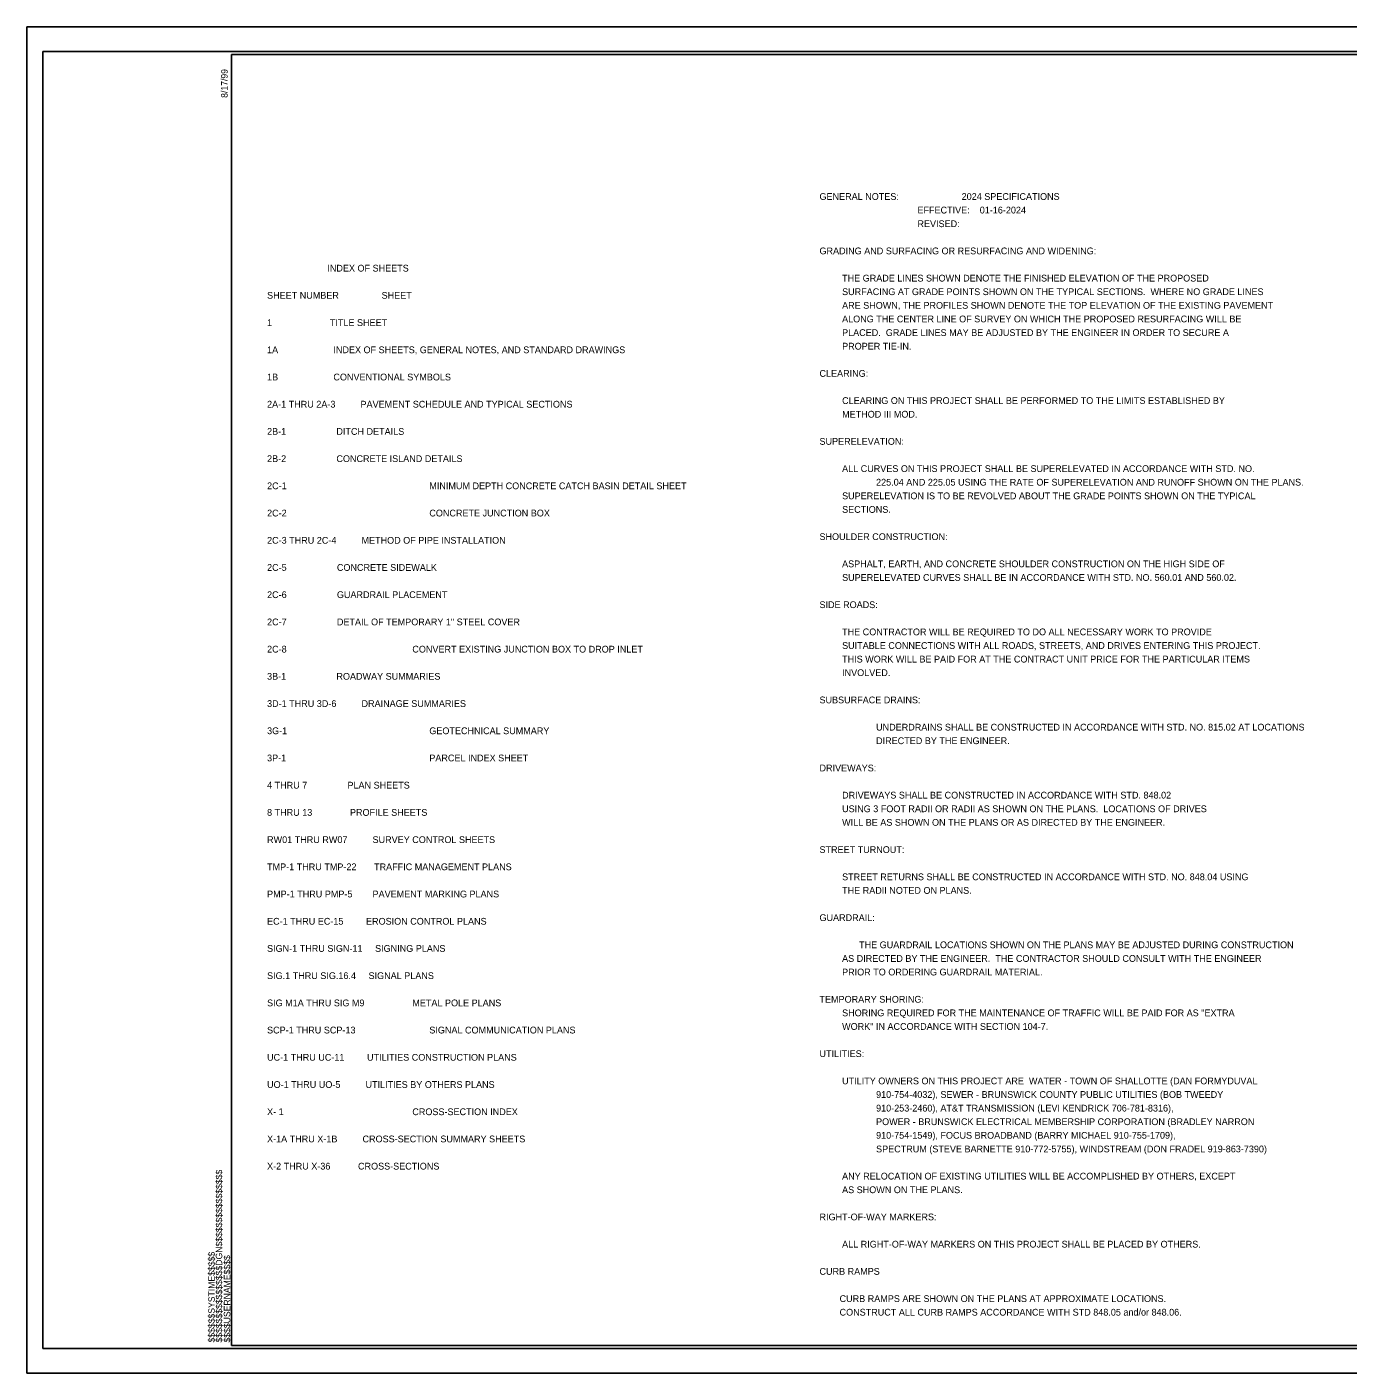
# Model space of a CAD drawing. Extents: x 779200 to 786346, y 600107 to 602297.
# Drawn here: x 780770 to 782920, y 600107 to 602297 of the extents above; entities that cross this region are included whole.
import ezdxf

# ---------------------------------------------------------------- set-up
doc = ezdxf.new("R2010")
doc.units = 0
for name, color, linetype in [('Sheet Border Standard 30in CELL', 7, 'Continuous'), ('Sheet Data Field CELL', 7, 'Continuous'), ('Sheet Plot Border Inside CELL', 7, 'Continuous'), ('Sheet Sticker Preliminary CELL', 7, 'Continuous')]:
    doc.layers.add(name, color=color, linetype=linetype)

msp = doc.modelspace()

# ---------------------------------------------------------------- linework, layer by layer
at = {"layer": 'Sheet Border Standard 30in CELL'}
msp.add_line((781103.3, 602251.7), (781103.3, 602251.7), dxfattribs=at)
msp.add_lwpolyline([(784103.3, 602251.7), (781103.3, 602251.7), (781103.3, 600151.7), (784103.3, 600151.7)], close=True, dxfattribs=at)
at = {"layer": 'Sheet Data Field CELL'}
msp.add_lwpolyline([(780770.3, 600106.7), (784137.3, 600106.7), (784137.3, 602296.7), (780770.3, 602296.7)], close=True, dxfattribs=at)
at = {"layer": 'Sheet Plot Border Inside CELL'}
msp.add_lwpolyline([(780796.3, 600146.7), (784128.3, 600146.7), (784128.3, 602256.7), (780796.3, 602256.7)], close=True, dxfattribs=at)

# ---------------------------------------------------------------- texts
at = {"layer": 'Sheet Border Standard 30in CELL'}
for s, p in [('8/17/99', (781096.8, 602181.3)), ('$$$$$$$$$$$$$$$$DGN$$$$$$$$$$$$$$$$', (781088, 600156.4)), ('$$$$$$SYSTIME$$$$$', (781075.9, 600156.4)), ('$$$$USERNAME$$$$', (781101.1, 600156.4))]:
    msp.add_text(s, height=10.5, rotation=90, dxfattribs=at).set_placement(p)
at = {"layer": 'Sheet Sticker Preliminary CELL'}
for s, p in [('GENERAL NOTES:                         2024 SPECIFICATIONS', (782059.8, 602015.3)), ('                                       EFFECTIVE:    01-16-2024', (782059.8, 601993.2)), ('                                       REVISED:      ', (782059.8, 601971)), ('GRADING AND SURFACING OR RESURFACING AND WIDENING:  ', (782059.8, 601926.8)), ('                        INDEX OF SHEETS ', (781161, 601898.7)), ('         THE GRADE LINES SHOWN DENOTE THE FINISHED ELEVATION OF THE PROPOSED ', (782059.8, 601882.5)), ('SHEET NUMBER                 SHEET   ', (781161, 601854.5)), ('         SURFACING AT GRADE POINTS SHOWN ON THE TYPICAL SECTIONS.  WHERE NO GRADE LINES ', (782059.8, 601860.4)), ('         ARE SHOWN, THE PROFILES SHOWN DENOTE THE TOP ELEVATION OF THE EXISTING PAVEMENT ', (782059.8, 601838.2)), ('1                       TITLE SHEET', (781161, 601810.2)), ('         ALONG THE CENTER LINE OF SURVEY ON WHICH THE PROPOSED RESURFACING WILL BE ', (782059.8, 601816.1)), ('         PLACED.  GRADE LINES MAY BE ADJUSTED BY THE ENGINEER IN ORDER TO SECURE A ', (782059.8, 601793.9)), ('1A                      INDEX OF SHEETS, GENERAL NOTES, AND STANDARD DRAWINGS', (781161, 601765.9)), ('         PROPER TIE-IN.  ', (782059.8, 601771.8)), ('1B                      CONVENTIONAL SYMBOLS ', (781161, 601721.6)), ('CLEARING:  ', (782059.8, 601727.5)), ('2A-1 THRU 2A-3          PAVEMENT SCHEDULE AND TYPICAL SECTIONS', (781161, 601677.4)), ('         CLEARING ON THIS PROJECT SHALL BE PERFORMED TO THE LIMITS ESTABLISHED BY ', (782059.8, 601683.3)), ('         METHOD III MOD.', (782059.8, 601661.1)), ('2B-1                    DITCH DETAILS', (781161, 601633.1)), ('SUPERELEVATION:  ', (782059.8, 601616.9)), ('2B-2                    CONCRETE ISLAND DETAILS', (781161, 601588.8)), ('         ALL CURVES ON THIS PROJECT SHALL BE SUPERELEVATED IN ACCORDANCE WITH STD. NO.', (782059.8, 601572.6)), ('2C-1 ', (781161, 601544.6)), ('MINIMUM DEPTH CONCRETE CATCH BASIN DETAIL SHEET', (781425, 601544.6)), (' 225.04 AND 225.05 USING THE RATE OF SUPERELEVATION AND RUNOFF SHOWN ON THE PLANS.', (782147.8, 601550.5)), ('         SUPERELEVATION IS TO BE REVOLVED ABOUT THE GRADE POINTS SHOWN ON THE TYPICAL ', (782059.8, 601528.3)), ('2C-2 ', (781161, 601500.3)), ('CONCRETE JUNCTION BOX', (781425, 601500.3)), ('         SECTIONS.  ', (782059.8, 601506.2)), ('2C-3 THRU 2C-4          METHOD OF PIPE INSTALLATION', (781161, 601456)), ('SHOULDER CONSTRUCTION:  ', (782059.8, 601461.9)), ('2C-5                    CONCRETE SIDEWALK', (781161, 601411.8)), ('         ASPHALT, EARTH, AND CONCRETE SHOULDER CONSTRUCTION ON THE HIGH SIDE OF', (782059.8, 601417.7)), ('         SUPERELEVATED CURVES SHALL BE IN ACCORDANCE WITH STD. NO. 560.01 AND 560.02.', (782059.8, 601395.5)), ('2C-6                    GUARDRAIL PLACEMENT', (781161, 601367.5)), ('SIDE ROADS:  ', (782059.8, 601351.2)), ('2C-7                    DETAIL OF TEMPORARY 1" STEEL COVER', (781161, 601323.2)), ('         THE CONTRACTOR WILL BE REQUIRED TO DO ALL NECESSARY WORK TO PROVIDE ', (782059.8, 601307)), ('2C-8', (781161, 601278.9)), ('    CONVERT EXISTING JUNCTION BOX TO DROP INLET ', (781381, 601278.9)), ('         SUITABLE CONNECTIONS WITH ALL ROADS, STREETS, AND DRIVES ENTERING THIS PROJECT.  ', (782059.8, 601284.8)), ('         THIS WORK WILL BE PAID FOR AT THE CONTRACT UNIT PRICE FOR THE PARTICULAR ITEMS ', (782059.8, 601262.7)), ('3B-1                    ROADWAY SUMMARIES', (781161, 601234.7)), ('         INVOLVED.', (782059.8, 601240.6)), ('3D-1 THRU 3D-6          DRAINAGE SUMMARIES', (781161, 601190.4)), ('SUBSURFACE DRAINS:', (782059.8, 601196.3)), ('3G-1', (781161, 601146.1)), ('GEOTECHNICAL SUMMARY', (781425, 601146.1)), (' UNDERDRAINS SHALL BE CONSTRUCTED IN ACCORDANCE WITH STD. NO. 815.02 AT LOCATIONS', (782147.8, 601152)), (' DIRECTED BY THE ENGINEER.   ', (782147.8, 601129.9)), ('3P-1                    ', (781161, 601101.9)), ('PARCEL INDEX SHEET', (781425, 601101.9)), ('DRIVEWAYS:  ', (782059.8, 601085.6)), ('4 THRU 7                PLAN SHEETS', (781161, 601057.6)), ('         DRIVEWAYS SHALL BE CONSTRUCTED IN ACCORDANCE WITH STD. 848.02', (782059.8, 601041.4)), ('8 THRU 13               PROFILE SHEETS', (781161, 601013.3)), ('         USING 3 FOOT RADII OR RADII AS SHOWN ON THE PLANS.  LOCATIONS OF DRIVES', (782059.8, 601019.2)), ('         WILL BE AS SHOWN ON THE PLANS OR AS DIRECTED BY THE ENGINEER.  ', (782059.8, 600997.1)), ('RW01 THRU RW07          SURVEY CONTROL SHEETS', (781161, 600969)), ('STREET TURNOUT:  ', (782059.8, 600952.8)), ('TMP-1 THRU TMP-22       TRAFFIC MANAGEMENT PLANS', (781161, 600924.8)), ('         STREET RETURNS SHALL BE CONSTRUCTED IN ACCORDANCE WITH STD. NO. 848.04 USING ', (782059.8, 600908.5)), ('         THE RADII NOTED ON PLANS.', (782059.8, 600886.4)), ('PMP-1 THRU PMP-5        PAVEMENT MARKING PLANS', (781161, 600880.5)), ('GUARDRAIL:', (782059.8, 600842.1)), ('EC-1 THRU EC-15         EROSION CONTROL PLANS', (781161, 600836.2)), ('     THE GUARDRAIL LOCATIONS SHOWN ON THE PLANS MAY BE ADJUSTED DURING CONSTRUCTION', (782103.8, 600797.9)), ('SIGN-1 THRU SIGN-11     SIGNING PLANS', (781161, 600792)), ('         AS DIRECTED BY THE ENGINEER.  THE CONTRACTOR SHOULD CONSULT WITH THE ENGINEER', (782059.8, 600775.7)), ('         PRIOR TO ORDERING GUARDRAIL MATERIAL.  ', (782059.8, 600753.6)), ('SIG.1 THRU SIG.16.4     SIGNAL PLANS', (781161, 600747.7)), ('TEMPORARY SHORING:', (782059.8, 600709.3)), ('SIG M1A THRU SIG M9', (781161, 600703.4)), ('    METAL POLE PLANS', (781381, 600703.4)), ('         SHORING REQUIRED FOR THE MAINTENANCE OF TRAFFIC WILL BE PAID FOR AS "EXTRA', (782059.8, 600687.2)), ('         WORK" IN ACCORDANCE WITH SECTION 104-7.    ', (782059.8, 600665.1)), ('SCP-1 THRU SCP-13', (781161, 600659.2)), ('SIGNAL COMMUNICATION PLANS', (781425, 600659.2)), ('UTILITIES:  ', (782059.8, 600620.8)), ('UC-1 THRU UC-11         UTILITIES CONSTRUCTION PLANS', (781161, 600614.9)), ('         UTILITY OWNERS ON THIS PROJECT ARE  WATER - TOWN OF SHALLOTTE (DAN FORMYDUVAL', (782059.8, 600576.5)), ('UO-1 THRU UO-5          UTILITIES BY OTHERS PLANS', (781161, 600570.6)), (' 910-754-4032), SEWER - BRUNSWICK COUNTY PUBLIC UTILITIES (BOB TWEEDY', (782147.8, 600554.4)), (' 910-253-2460), AT&T TRANSMISSION (LEVI KENDRICK 706-781-8316),', (782147.8, 600532.2)), ('X- 1', (781161, 600526.3)), ('    CROSS-SECTION INDEX', (781381, 600526.3)), (' POWER - BRUNSWICK ELECTRICAL MEMBERSHIP CORPORATION (BRADLEY NARRON', (782147.8, 600510.1)), (' 910-754-1549), FOCUS BROADBAND (BARRY MICHAEL 910-755-1709),', (782147.8, 600488)), ('X-1A THRU X-1B          CROSS-SECTION SUMMARY SHEETS', (781161, 600482.1)), (' SPECTRUM (STEVE BARNETTE 910-772-5755), WINDSTREAM (DON FRADEL 919-863-7390)', (782147.8, 600465.8)), ('X-2 THRU X-36           CROSS-SECTIONS', (781161, 600437.8)), ('         ANY RELOCATION OF EXISTING UTILITIES WILL BE ACCOMPLISHED BY OTHERS, EXCEPT ', (782059.8, 600421.6)), ('         AS SHOWN ON THE PLANS.  ', (782059.8, 600399.4)), ('RIGHT-OF-WAY MARKERS:  ', (782059.8, 600355.2)), ('         ALL RIGHT-OF-WAY MARKERS ON THIS PROJECT SHALL BE PLACED BY OTHERS.  ', (782059.8, 600310.9)), ('CURB RAMPS', (782059.8, 600266.6)), ('        CURB RAMPS ARE SHOWN ON THE PLANS AT APPROXIMATE LOCATIONS.', (782059.8, 600222.3)), ('        CONSTRUCT ALL CURB RAMPS ACCORDANCE WITH STD 848.05 and/or 848.06.', (782059.8, 600200.2))]:
    msp.add_text(s, height=11, dxfattribs=at).set_placement(p)

doc.saveas('drawing.dxf')
